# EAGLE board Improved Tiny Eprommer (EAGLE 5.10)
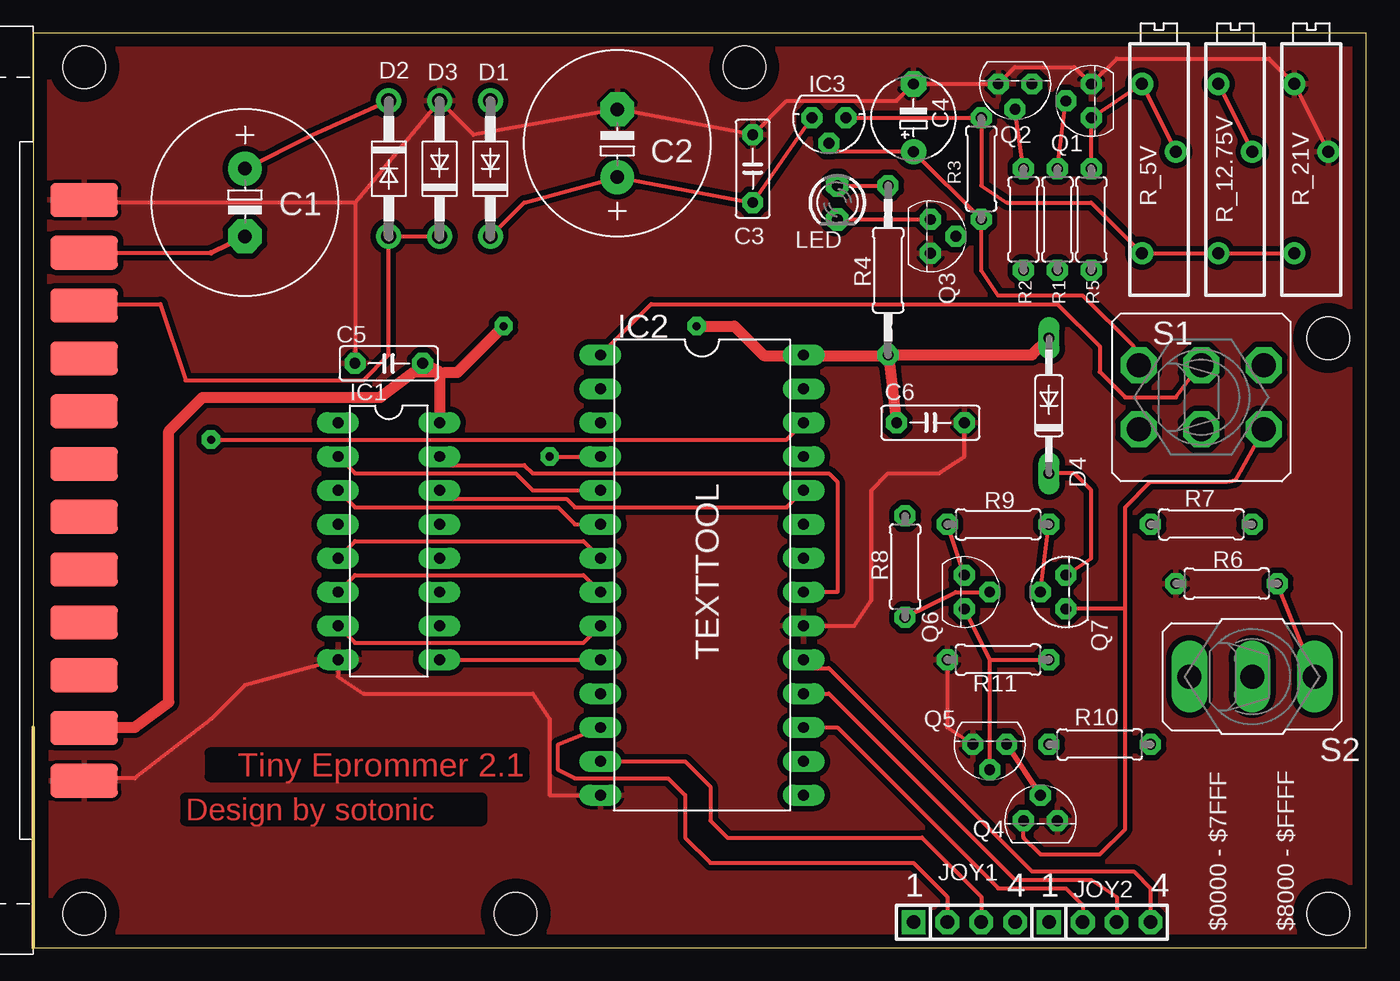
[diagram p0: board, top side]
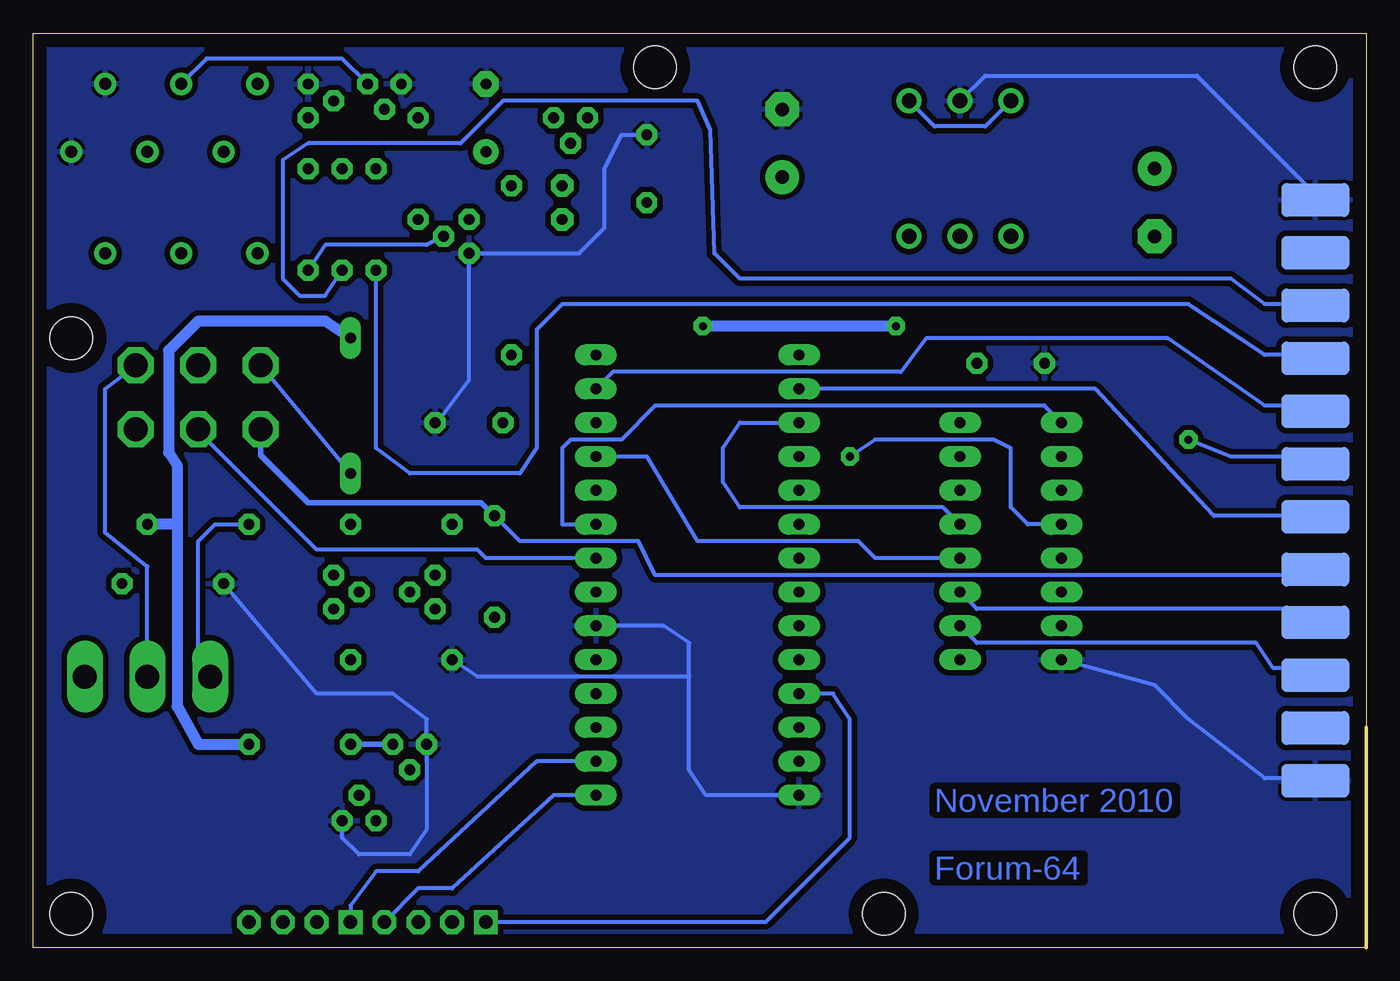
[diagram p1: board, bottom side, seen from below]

Size 100 x 68.57 mm. Coordinates in mm from the lower left corner, seen from the top.
Outline: 0,16.51 0,0 100,0 100,68.57 0,68.57 0,16.51
Copper layers (1*16): Top 0.035mm / dielectric 1.5mm / Bottom 0.035mm
Design rules "BWieck": minimum track width 12mil, minimum drill 24mil, track to track 12mil, track to pad 12mil, pad to pad 10mil, via to via 12mil, smd to smd 8mil, copper to edge 40mil, drill to drill 8mil, minimum pad ring 15mil, minimum via ring 15mil, stop-mask expansion 4mil, vias tented up to drill 0mil, thermal gap 10mil
Holes 3.2 mm at 97.16,2.54 97.16,45.72 53.34,66.04 36.2,2.54 3.81,66.04 3.81,2.54

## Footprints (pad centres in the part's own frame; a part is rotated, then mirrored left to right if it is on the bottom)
E5-13 = drill 1.016 pad 2.54 round: + -2.54,0 | drill 1.016 pad 2.54 octagon: - 2.54,0
C050-025X075 = drill 0.813 octagon: 1 -2.54,0; 2 2.54,0
E5-6 = drill 0.813 pad 1.905 round: + -2.54,0 | drill 0.813 pad 1.905 octagon: - 2.54,0
UPS24CONN = smd 2.54 x 5.08: 1 -21.779,-1.27; 2 -17.819,-1.27; 3 -13.859,-1.27; 4 -9.899,-1.27; 5 -5.939,-1.27; 6 -1.979,-1.27; 7 1.981,-1.27; 8 5.941,-1.27; 9 9.901,-1.27; 10 13.861,-1.27; 11 17.821,-1.27; 12 21.781,-1.27 | smd 2.54 x 5.08 bottom: A -21.779,-1.27; B -17.819,-1.27; C -13.859,-1.27; D -9.899,-1.27; E -5.939,-1.27; F -1.979,-1.27; H 1.981,-1.27; J 5.941,-1.27; K 9.901,-1.27; L 13.861,-1.27; M 17.821,-1.27; N 21.781,-1.27
DO41-10 = drill 1.118 round: A 5.08,0; C -5.08,0
DO35-10 = drill 0.813 long: A 5.08,0; C -5.08,0
DIL16 = drill 0.813 long: 1 -8.89,-3.81; 2 -6.35,-3.81; 3 -3.81,-3.81; 4 -1.27,-3.81; 5 1.27,-3.81; 6 3.81,-3.81; 7 6.35,-3.81; 8 8.89,-3.81; 9 8.89,3.81; 10 6.35,3.81; 11 3.81,3.81; 12 1.27,3.81; 13 -1.27,3.81; 14 -3.81,3.81; 15 -6.35,3.81; 16 -8.89,3.81
DIL28-6 = drill 0.813 long: 1 -16.51,-7.62; 2 -13.97,-7.62; 3 -11.43,-7.62; 4 -8.89,-7.62; 5 -6.35,-7.62; 6 -3.81,-7.62; 7 -1.27,-7.62; 8 1.27,-7.62; 9 3.81,-7.62; 10 6.35,-7.62; 11 8.89,-7.62; 12 11.43,-7.62; 13 13.97,-7.62; 14 16.51,-7.62; 15 16.51,7.62; 16 13.97,7.62; 17 11.43,7.62; 18 8.89,7.62; 19 6.35,7.62; 20 3.81,7.62; 21 1.27,7.62; 22 -1.27,7.62; 23 -3.81,7.62; 24 -6.35,7.62; 25 -8.89,7.62; 26 -11.43,7.62; 27 -13.97,7.62; 28 -16.51,7.62
317L = drill 0.813 octagon: 1 -1.27,0; 2 0,1.905; 3 1.27,0
1X04 = drill 1.016 square: 1 -3.81,0 | drill 1.016 octagon: 2 -1.27,0; 3 1.27,0; 4 3.81,0
LED3MM = drill 0.813 pad 1.676 octagon: A -1.27,0; K 1.27,0
TO92 = drill 0.813 octagon: 1 1.27,0; 2 0,1.905; 3 -1.27,0
0207/7 = drill 0.813 octagon: 1 -3.81,0; 2 3.81,0
0207/12 = drill 0.813 octagon: 1 -6.35,0; 2 6.35,0
RTRIMT18 = drill 0.9 round: 1 -7.62,1.27; 2 0,-1.27; 3 5.08,1.27
M9040P2 = drill 1.803 octagon: 1 -2.413,4.699; 2 -2.413,0; 3 -2.413,-4.699; 4 2.413,4.699; 5 2.413,0; 6 2.413,-4.699
M9040P = drill 1.803 long: 1 0,4.699; 2 0,0; 3 0,-4.699

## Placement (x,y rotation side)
C1  470µ 63V  [E5-13]  15.88,55.88 270 top
C2  470µ 63V  [E5-13]  43.81,60.32 90 top
C3  100n  [C050-025X075]  53.98,58.42 90 top
C4  1µF  [E5-6]  66.04,62.23 90 top
C5  100n  [C050-025X075]  26.67,43.81 180 top
C6  100n  [C050-025X075]  67.31,39.37 0 top
CN1  USERPORT-C64-CONN  [UPS24CONN]  2.54,34.29 90 top
D1  1N4007  [DO41-10]  34.29,58.42 90 top
D2  1N4007  [DO41-10]  26.67,58.42 270 top
D3  3x1N4007  [DO41-10]  30.48,58.42 90 top
D4  1N4148  [DO35-10]  76.2,40.64 90 top
IC1  4040N  [DIL16]  26.67,30.48 270 top
IC2  [DIL28-6]  50.16,27.94 270 top
IC3  [317L]  59.69,62.23 180 top
JOY1  [1X04]  69.85,1.9 0 top
JOY2  [1X04]  80.01,1.9 0 top
LED  2mA  [LED3MM]  60.33,55.88 270 top
Q1  BC547B  [TO92]  79.38,63.5 90 top
Q2  BC547B  [TO92]  73.66,64.77 180 top
Q3  BC547B  [TO92]  67.31,53.34 270 top
Q4  BC547B  [TO92]  75.56,9.53 0 top
Q5  BC547B  [TO92]  71.75,15.24 180 top
Q6  BC547B  [TO92]  69.85,26.67 270 top
Q7  BC557  [TO92]  77.47,26.67 90 top
R1  4k7  [0207/7]  76.83,54.61 90 top
R2  4k7  [0207/7]  74.3,54.61 90 top
R3  240R  [0207/7]  71.12,58.42 270 top
R4  1k5  [0207/12]  64.14,50.8 270 top
R5  27k  [0207/7]  79.38,54.61 270 top
R6  4k7  [0207/7]  89.53,27.3 180 top
R7  4k7  [0207/7]  87.63,31.75 0 top
R8  4k7  [0207/7]  65.41,28.57 270 top
R9  10k  [0207/7]  72.39,31.75 180 top
R10  10k  [0207/7]  80.01,15.24 0 top
R11  10k  [0207/7]  72.39,21.59 0 top
R_5V  1K Lin  [RTRIMT18]  84.45,59.69 90 top
R_12.75V  10k Lin  [RTRIMT18]  90.17,59.69 90 top
R_21V  5k Lin  [RTRIMT18]  95.89,59.69 90 top
S1  [M9040P2]  87.63,41.27 270 top
S2  [M9040P]  91.44,20.32 270 top

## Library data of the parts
C1-C6 R1-R11 R_5V R_12.75V R_21V = rcl
CN1 = 0RB_Commodore
D1-D4 = diode
IC1 = 40xx
IC2 = ic-package
IC3 = v-reg
JOY1 JOY2 = pinhead
LED = led
Q1-Q6 = transistor-npn
Q7 = transistor-pnp
S1 S2 = switch

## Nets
+5V: C5.1 C6.1 CN1.2 D4.A IC1.16 IC2.28 R4.2 R7.2 R10.2
GND: C2.- C3.2 C4.- C5.2 C6.2 CN1.1 CN1.12 CN1.A CN1.N D3.A IC1.8 IC2.14 IC2.20 Q1.1 Q2.1 Q3.1 Q4.1 Q5.1 R6.2 R11.1 R_21V.2 R_21V.3
N$1: IC2.22 S1.5
N$2: IC2.1 S1.2
N$3: S1.1 S2.2
N$4: Q4.2 Q5.3 R10.1
N$5: C1.- CN1.11
N$6: C1.+ D1.A D2.C
N$7: CN1.10 D2.A D3.C
N$9: C2.+ C3.1 D1.C IC3.3
N$10: R7.1 S2.3
N$11: CN1.E R8.1 S1.6
N$12: IC3.1 R3.1 R_5V.1 R_12.75V.1 R_21V.1
N$13: LED.A R4.1
N$14: LED.K Q3.3
N$15: CN1.L R1.1
N$16: Q1.2 R1.2
N$17: CN1.K R2.1
N$18: Q2.2 R2.2
N$19: Q1.3 R5.1 R_5V.2 R_5V.3
N$20: Q2.3 R_12.75V.2 R_12.75V.3
N$21: IC1.9 IC2.10
N$22: Q3.2 R5.2
N$23: R6.1 S2.1
N$24: CN1.C IC1.10
N$25: CN1.D IC1.11
N$26: IC1.7 IC2.9
N$27: IC1.6 IC2.8
N$28: IC1.5 IC2.7
N$29: IC1.3 IC2.6
N$30: IC1.2 IC2.5
N$31: IC1.4 IC2.4
N$32: IC1.13 IC2.3
N$33: IC1.12 IC2.25
N$34: IC1.14 IC2.24
N$35: IC1.15 IC2.21
N$36: IC1.1 IC2.23
N$37: CN1.F IC2.2
N$38: CN1.J IC2.27
N$39: CN1.H IC2.26
N$40: Q4.3 Q7.3 S1.4
N$41: IC2.13 JOY1.3
N$42: IC2.12 JOY1.2
N$43: IC2.11 JOY1.1
N$44: IC2.15 JOY1.4
N$45: Q5.2 Q6.1 R11.2
N$46: IC2.16 JOY2.1
N$47: IC2.17 JOY2.2
N$48: IC2.18 JOY2.3
N$49: IC2.19 JOY2.4
N$50: Q6.3 R9.2
N$51: Q7.2 R9.1
N$52: Q6.2 R8.2
VPP: C4.+ D4.C IC3.2 Q7.1 R3.2 S1.3

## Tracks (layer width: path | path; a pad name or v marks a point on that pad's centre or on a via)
+5V  (via drill 0.61)
  Top 0.305: 64.11,44.4 R4.2 | CN1.2 3.81,16.51 | 30.48,43.18 30.87,43.14
  Top 0.406: IC2.28 R4.2
  Top 0.813: 30.48,43.18 C5.1 | 30.48,43.18 IC1.16 | C6.1 R4.2 74.93,44.45 D4.A | 64.11,44.4 54.81,44.4 52.6,46.61 v49.77,46.61 | 3.81,16.51 7.62,16.51 10.16,18.41 10.16,38.73 12.7,41.27 26.04,41.27 28.57,43.18 30.48,43.18 | v35.28,46.61 31.82,43.14 30.87,43.14
  Bottom 0.813: R10.2 87.63,15.24 89.22,18.1 89.22,31.75 | 89.22,31.75 R7.2 | 89.22,31.75 89.22,36.2 89.86,37.14 89.86,44.76 87.63,46.99 78.11,46.99 D4.A | v35.28,46.61 v49.77,46.61
GND
  Top 0.305: R_21V.2 R_21V.3 92.71,66.67 81.28,66.67 Q1.1 78.11,66.04 73.66,66.04 Q2.1 C4.- 64.77,63.5 56.52,63.5 C3.2 C2.- 33.02,60.96 D3.A 24.13,55.88 | 24.13,55.88 3.81,55.88 CN1.N | 24.13,55.88 C5.2 | Q5.1 68.58,16.51 R11.1 | CN1.A 3.81,12.7 7.62,12.7 13.34,17.14 15.88,19.68 IC1.8 22.86,20.32 24.77,19.05 37.47,19.05 38.73,17.14 38.73,11.43 IC2.14 | C6.2 69.85,36.83 67.94,35.56 64.14,35.56 62.87,34.29 62.87,26.04 61.59,24.13 IC2.20
  Bottom 0.305: D3.A 28.57,65.41 12.7,65.41 3.81,56.51 CN1.N | Q4.1 76.83,8.26 75.56,6.99 71.75,6.99 70.48,8.89 Q5.1 70.48,17.14 73.03,19.05 78.74,19.05 R6.2 | IC1.8 15.88,19.68 13.34,17.14 7.62,12.7 3.81,12.7 CN1.A | C6.2 69.22,40 67.31,42.54 Q3.1 59.05,52.07 57.15,53.97 57.15,58.42 55.88,60.96 C3.2 | 50.8,20.32 50.8,22.86 52.7,24.13 IC2.20 | IC2.14 49.53,11.43 50.8,13.34 50.8,20.32 | R11.1 66.67,20.32 50.8,20.32
  pour Top (isolate 0.406): 0,68.58 99.69,68.58 99.69,0 0,0
  pour Bottom (isolate 0.406): 0,68.58 100.33,68.58 100.33,0 0,0
N$1
  Bottom 0.305: IC2.22 66.04,29.21 66.67,29.84 78.74,29.84 87.63,38.73 S1.5
N$2
  Top 0.305: IC2.1 46.35,48.26 76.83,48.26 80.01,45.08 80.01,43.18 81.92,41.27 85.72,41.27 87.63,43.81 S1.2
N$3
  Bottom 0.305: S2.2 91.44,28.57 94.61,31.11 94.61,41.91 S1.1
N$4
  Top 0.406: Q4.2 Q5.3
  Bottom 0.406: Q5.3 R10.1
N$5
  Top 0.305: CN1.11 13.34,52.11
  Top 0.406: 13.34,52.11 C1.-
N$6
  Top 0.305: D2.C 20.95,60.96 C1.+
  Bottom 0.305: D1.A 32.38,61.59 28.57,61.59 D2.C
N$7
  Top 0.305: D3.C D2.A 26.67,44.45 24.77,42.54 11.43,42.54 9.53,48.26 3.81,48.26 CN1.10
N$9
  Top 0.305: IC3.3 C3.1 C2.+ 36.83,55.88 D1.C
N$10
  Bottom 0.305: R7.1 86.36,31.75 87.63,30.48 87.63,20.32 S2.3
N$11
  Bottom 0.305: R8.1 63.5,30.48 54.61,30.48 53.34,27.94 3.81,27.94 CN1.E
  Bottom 0.406: R8.1 66.4,33.38 79.38,33.38 82.93,36.93 S1.6
N$12
  Top 0.305: IC3.1 R3.1 71.12,57.15 73.03,55.88 79.38,55.88 R_5V.1 R_12.75V.1 R_21V.1
N$13
  Top 0.305: LED.A R4.1
N$14
  Top 0.305: LED.K Q3.3
N$15
  Bottom 0.305: R1.1 78.11,48.89 80.01,48.89 81.28,50.16 81.28,59.05 79.38,60.32 67.94,60.32 64.77,63.5 50.16,63.5 49.21,61.28 48.9,52.07 46.99,50.16 10.16,50.16 7.62,48.26 5.71,48.26 CN1.L
N$16
  Top 0.305: R1.2 Q1.2
N$17
  Bottom 0.305: R2.1 74.3,37.46 71.75,35.56 63.5,35.56 62.23,37.46 62.23,46.35 60.33,48.26 13.34,48.26 7.62,44.45 3.81,44.45 CN1.K
N$18
  Top 0.305: R2.2 Q2.2
N$19
  Top 0.305: R5.1 Q1.3 R_5V.3 R_5V.2
N$20
  Top 0.305: R_12.75V.3 R_12.75V.2
  Bottom 0.305: Q2.3 76.83,66.67 87,66.67 R_12.75V.3
N$21
  Top 0.305: IC1.9 IC2.10
N$22
  Bottom 0.305: Q3.2 70.48,52.7 78.11,52.7 R5.2
N$23
  Top 0.305: S2.1 R6.1
N$24
  Bottom 0.305: IC1.10 29.21,22.86 8.26,22.86 6.99,20.96 3.81,20.96 CN1.C
N$25
  Bottom 0.305: IC1.11 29.21,25.4 4.45,25.4 3.81,24.77 CN1.D
N$26
  Top 0.305: IC1.7 24.13,22.86 41.27,22.86 IC2.9
N$27
  Top 0.305: IC1.6 24.13,27.94 41.27,27.94 IC2.8
N$28
  Top 0.305: IC1.5 24.13,30.48 41.27,30.48 IC2.7
N$29
  Top 0.305: IC1.3 24.13,33.02 39.37,33.02 40.64,31.75 IC2.6
N$30
  Top 0.305: IC1.2 24.13,35.56 36.2,35.56 37.47,34.29 IC2.5
N$31  (via drill 0.61)
  Top 0.305: v38.73,36.83 IC2.4
  Bottom 0.305: IC1.4 25.4,31.75 26.67,33.02 26.67,37.46 27.94,38.1 36.83,38.1 v38.73,36.83
N$32
  Bottom 0.305: IC1.13 31.75,33.02 46.99,33.02 48.26,34.92 48.26,37.46 46.99,39.37 IC2.3
N$33
  Bottom 0.305: IC1.12 36.83,29.21 38.1,30.48 50.16,30.48 53.98,36.83 IC2.25
N$34
  Top 0.305: IC1.14 31.11,33.65 40.01,33.65 40.64,33.02 56.52,33.02 IC2.24
N$35
  Top 0.305: IC1.15 31.11,36.2 36.83,36.2 37.47,35.56 59.69,35.56 60.33,34.92 60.33,26.67 IC2.21
N$36
  Bottom 0.305: IC1.1 24.13,40.64 53.34,40.64 55.88,38.1 59.69,38.1 60.33,37.46 60.33,31.75 IC2.23
N$37
  Bottom 0.305: IC2.2 20.32,41.91 11.43,32.38 3.81,32.38 CN1.F
N$38
  Bottom 0.305: IC2.27 56.52,43.18 34.92,43.18 33.02,45.7 14.89,45.7 7.62,40.64 3.81,40.64 CN1.J
N$39  (via drill 0.61)
  Top 0.305: IC2.26 56.52,38.1 v13.34,38.1
  Bottom 0.305: v13.34,38.1 10.16,36.83 3.81,36.83 CN1.H
N$40
  Top 0.305: Q4.3 74.3,8.26 75.56,6.99 80.01,6.99 81.92,8.89 81.92,25.4 | 81.92,25.4 Q7.3 | 81.92,25.4 81.92,33.02 83.82,34.92 89.53,34.92 90.17,35.05 S1.4
N$41
  Top 0.305: JOY1.3 71.12,3.81 66.67,8.26 52.07,8.26 50.8,9.53 50.8,12.07 48.9,13.97 IC2.13
N$42
  Top 0.305: IC2.12 39.37,15.24 39.37,13.34 40.64,12.7 47.62,12.7 48.9,11.43 48.9,8.26 50.8,6.35 66.04,6.35 68.58,3.81 JOY1.2
N$43
  Bottom 0.305: IC2.11 40.01,19.05 38.73,17.14 38.73,8.26 45.09,1.9 JOY1.1
N$44
  Bottom 0.305: IC2.15 60.96,11.43 68.58,4.45 71.12,4.45 JOY1.4
N$45
  Top 0.305: 71.75,21.59 R11.2 | Q5.2 71.75,21.59 | 71.75,21.59 Q6.1
N$46
  Bottom 0.305: IC2.16 62.23,13.97 71.12,5.71 74.3,5.71 76.2,3.18 JOY2.1
N$47
  Top 0.305: IC2.17 60.33,16.51 72.39,4.45 77.47,4.45 78.74,3.18 JOY2.2
N$48
  Top 0.305: IC2.18 59.69,19.05 73.66,5.08 79.38,5.08 81.28,3.81 JOY2.3
N$49
  Top 0.305: IC2.19 58.42,20.96 59.69,20.96 74.93,5.71 82.55,5.71 83.82,4.45 JOY2.4
N$50
  Top 0.305: Q6.3 R9.2
N$51
  Top 0.305: Q7.2 R9.1
N$52
  Top 0.305: R8.2 69.22,26.67 Q6.2
VPP
  Top 0.305: IC3.2 60.33,59.69 C4.+ R3.2 71.12,50.8 72.39,48.89 78.74,48.89 82.55,45.08 S1.3 | Q7.1 79.38,29.21 79.38,34.29 78.11,35.56 D4.C
  Bottom 0.305: D4.C 82.55,43.18 S1.3

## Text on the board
Top: Tiny Eprommer 2.1 | Design by sotonic
Bottom: November 2010 | Forum-64
tPlace: TEXTTOOL | 1 | 4 | 1 | 4 | $0000 - $7FFF | $8000 - $FFFF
